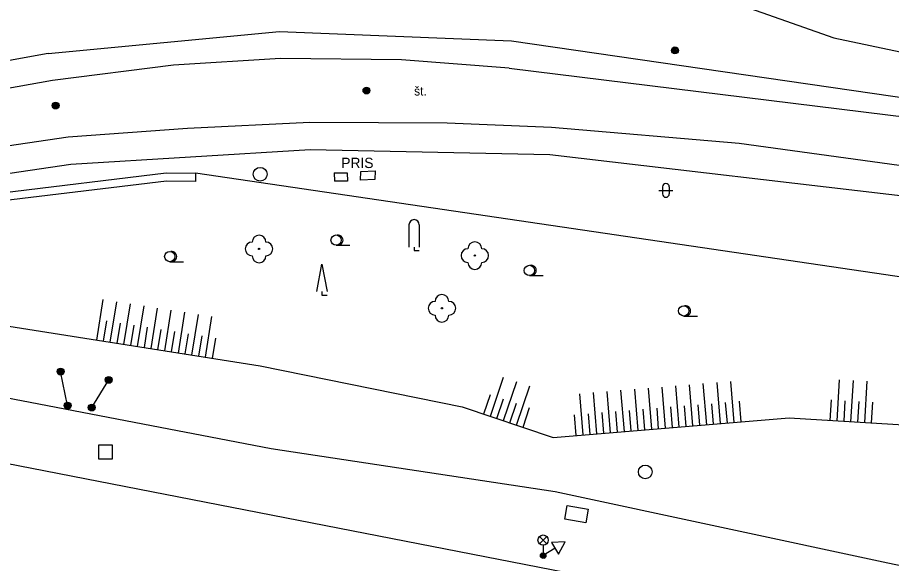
# Model space of a CAD drawing. Extents: x -599951 to -598963, y -1164095 to -1162939.
# Drawn here: x -599846.5 to -599783, y -1163048.3 to -1163008.7 of the extents above; entities that cross this region are included whole.
import ezdxf

# ---------------------------------------------------------------- set-up
doc = ezdxf.new("R2010")
doc.units = 0
for name, color, linetype in [('Level 10', 7, 'Continuous'), ('Level 11', 7, 'Continuous'), ('Level 13', 7, 'Continuous'), ('Level 14', 7, 'Continuous'), ('Level 15', 7, 'Continuous'), ('Level 22', 7, 'Continuous'), ('Level 24', 7, 'Continuous'), ('Level 25', 7, 'Continuous'), ('Level 26', 7, 'Continuous'), ('Level 27', 7, 'Continuous'), ('Level 33', 7, 'Continuous'), ('Level 34', 7, 'Continuous'), ('Level 36', 7, 'Continuous'), ('Level 40', 7, 'Continuous'), ('Level 41', 7, 'Continuous'), ('Level 7', 7, 'Continuous')]:
    doc.layers.add(name, color=color, linetype=linetype)

msp = doc.modelspace()

# ---------------------------------------------------------------- linework, layer by layer
at = {"layer": 'Level 10'}
msp.add_lwpolyline([(-599860, -1163038.58), (-599806.72, -1163048.96)], dxfattribs=at)
at = {"layer": 'Level 11'}
for points in [[(-599844.28, -1163011.27), (-599827.48, -1163009.67)], [(-599827.48, -1163009.67), (-599810.62, -1163010.35)], [(-599810.62, -1163010.35), (-599779.77, -1163014.83)], [(-599844.28, -1163011.27), (-599863.42, -1163014.74)], [(-599842.62, -1163019.32), (-599825.24, -1163018.26)], [(-599825.24, -1163018.26), (-599807.84, -1163018.62)], [(-599807.84, -1163018.62), (-599780.96, -1163021.77)], [(-599852.17, -1163020.73), (-599842.62, -1163019.32)], [(-599842.86, -1163036.86), (-599843.37, -1163034.39)], [(-599783.29, -1163048.32), (-599807.46, -1163043.13), (-599828.09, -1163040.01), (-599852.4, -1163035.32)], [(-599841.11, -1163037), (-599839.88, -1163034.99)], [(-599806.58, -1163044.13), (-599805.07, -1163044.39), (-599805.24, -1163045.38), (-599806.75, -1163045.12), (-599806.58, -1163044.13)], [(-599752.45, -1163054.58), (-599771.39, -1163050.77), (-599783.29, -1163048.32)]]:
    msp.add_lwpolyline(points, dxfattribs=at)
at = {"layer": 'Level 13'}
for points in [[(-599827.41, -1163011.65), (-599835.18, -1163012.12)], [(-599818.61, -1163011.73), (-599827.41, -1163011.65)], [(-599810.8, -1163012.34), (-599818.61, -1163011.73)], [(-599835.18, -1163012.12), (-599843.96, -1163013.24)], [(-599810.8, -1163012.34), (-599779.96, -1163016.14)], [(-599843.96, -1163013.24), (-599853.58, -1163014.95)], [(-599834.15, -1163016.7), (-599825.28, -1163016.27)], [(-599825.28, -1163016.27), (-599815.29, -1163016.32)], [(-599815.29, -1163016.32), (-599807.72, -1163016.62)], [(-599842.82, -1163017.33), (-599834.15, -1163016.7)], [(-599807.72, -1163016.62), (-599794.09, -1163017.79)], [(-599852.52, -1163018.77), (-599842.82, -1163017.33)], [(-599794.09, -1163017.79), (-599780.54, -1163019.65)]]:
    msp.add_lwpolyline(points, dxfattribs=at)
at = {"layer": 'Level 14'}
for points in [[(-599808.34, -1163001.79), (-599796.36, -1163006.89), (-599787.21, -1163010.15), (-599762.56, -1163015.35), (-599750.18, -1163017.87)], [(-599768.65, -1163029.54), (-599833.57, -1163019.98)], [(-599850.84, -1163030.51), (-599828.89, -1163033.97), (-599814.2, -1163036.96), (-599807.6, -1163039.17), (-599790.47, -1163037.76), (-599781.75, -1163038.28), (-599775.55, -1163038.66), (-599752.45, -1163054.58)]]:
    msp.add_lwpolyline(points, dxfattribs=at)
at = {"layer": 'Level 15'}
for points in [[(-599840.74, -1163032.1), (-599840.28, -1163029.15)], [(-599839.76, -1163032.26), (-599839.29, -1163029.31)], [(-599838.77, -1163032.41), (-599838.3, -1163029.46)], [(-599837.78, -1163032.57), (-599837.31, -1163029.62)], [(-599836.79, -1163032.72), (-599836.33, -1163029.77)], [(-599835.81, -1163032.88), (-599835.34, -1163029.92)], [(-599834.82, -1163033.04), (-599834.35, -1163030.08)], [(-599833.83, -1163033.19), (-599833.36, -1163030.23)], [(-599840.25, -1163032.18), (-599840.02, -1163030.7)], [(-599839.26, -1163032.34), (-599839.03, -1163030.86)], [(-599838.27, -1163032.49), (-599838.04, -1163031.01)], [(-599832.84, -1163033.35), (-599832.38, -1163030.39)], [(-599837.29, -1163032.65), (-599837.05, -1163031.17)], [(-599836.3, -1163032.8), (-599836.07, -1163031.32)], [(-599835.31, -1163032.96), (-599835.08, -1163031.48)], [(-599834.32, -1163033.11), (-599834.09, -1163031.64)], [(-599833.34, -1163033.27), (-599833.1, -1163031.79)], [(-599832.35, -1163033.43), (-599832.11, -1163031.95)], [(-599812.16, -1163037.63), (-599811.2, -1163034.79)], [(-599811.21, -1163037.95), (-599810.25, -1163035.11)], [(-599810.26, -1163038.27), (-599809.3, -1163035.43)], [(-599798.44, -1163038.42), (-599798.69, -1163035.43)], [(-599797.45, -1163038.33), (-599797.69, -1163035.34)], [(-599796.45, -1163038.25), (-599796.7, -1163035.26)], [(-599795.45, -1163038.17), (-599795.7, -1163035.18)], [(-599794.46, -1163038.09), (-599794.7, -1163035.1)], [(-599786.98, -1163037.97), (-599786.8, -1163034.99)], [(-599785.98, -1163038.03), (-599785.8, -1163035.04)], [(-599784.98, -1163038.09), (-599784.8, -1163035.09)], [(-599812.63, -1163037.47), (-599812.15, -1163036.05)], [(-599805.42, -1163038.99), (-599805.67, -1163036)], [(-599804.42, -1163038.91), (-599804.67, -1163035.92)], [(-599803.43, -1163038.83), (-599803.67, -1163035.84)], [(-599802.43, -1163038.74), (-599802.68, -1163035.75)], [(-599801.43, -1163038.66), (-599801.68, -1163035.67)], [(-599800.44, -1163038.58), (-599800.68, -1163035.59)], [(-599799.44, -1163038.5), (-599799.69, -1163035.51)], [(-599811.69, -1163037.79), (-599811.2, -1163036.37)], [(-599810.74, -1163038.11), (-599810.26, -1163036.69)], [(-599795.95, -1163038.21), (-599796.07, -1163036.72)], [(-599794.95, -1163038.13), (-599795.08, -1163036.63)], [(-599793.96, -1163038.05), (-599794.08, -1163036.55)], [(-599787.48, -1163037.94), (-599787.39, -1163036.45)], [(-599786.48, -1163038), (-599786.39, -1163036.51)], [(-599785.48, -1163038.06), (-599785.39, -1163036.56)], [(-599784.48, -1163038.12), (-599784.39, -1163036.62)], [(-599809.79, -1163038.43), (-599809.31, -1163037.01)], [(-599802.93, -1163038.78), (-599803.05, -1163037.29)], [(-599801.93, -1163038.7), (-599802.05, -1163037.21)], [(-599800.94, -1163038.62), (-599801.06, -1163037.13)], [(-599799.94, -1163038.54), (-599800.06, -1163037.04)], [(-599798.94, -1163038.46), (-599799.06, -1163036.96)], [(-599797.94, -1163038.38), (-599798.07, -1163036.88)], [(-599796.95, -1163038.29), (-599797.07, -1163036.8)], [(-599805.92, -1163039.03), (-599806.04, -1163037.54)], [(-599804.92, -1163038.95), (-599805.04, -1163037.45)], [(-599803.92, -1163038.87), (-599804.05, -1163037.37)]]:
    msp.add_lwpolyline(points, dxfattribs=at)
at = {"layer": 'Level 22'}
for centre in [(-599828.96, -1163025.48), (-599813.29, -1163025.96), (-599815.68, -1163029.79)]:
    msp.add_circle(centre, 0.05, dxfattribs=at)
for centre, start, end in [((-599828.96, -1163024.98), 0, 180), ((-599829.46, -1163025.48), 90, 270), ((-599828.46, -1163025.48), 270, 90), ((-599813.29, -1163025.46), 0, 180), ((-599813.79, -1163025.96), 90, 270), ((-599812.79, -1163025.96), 270, 90), ((-599828.96, -1163025.98), 180, 0), ((-599813.29, -1163026.46), 180, 0), ((-599815.68, -1163029.29), 0, 180), ((-599816.18, -1163029.79), 90, 270), ((-599815.18, -1163029.79), 270, 90), ((-599815.68, -1163030.29), 180, 0)]:
    msp.add_arc(centre, 0.5, start, end, dxfattribs=at)
at = {"layer": 'Level 24'}
for points in [[(-599823.51, -1163019.96), (-599822.55, -1163019.96), (-599822.53, -1163020.55), (-599823.49, -1163020.55)], [(-599823.51, -1163019.96), (-599823.49, -1163020.55)], [(-599821.58, -1163019.85), (-599820.53, -1163019.81), (-599820.54, -1163020.44), (-599821.59, -1163020.48), (-599821.58, -1163019.85)]]:
    msp.add_lwpolyline(points, dxfattribs=at)
at = {"layer": 'Level 25'}
for centre, radius in [((-599798.76, -1163011.05), 0.25), ((-599798.76, -1163011.05), 0.2), ((-599798.76, -1163011.05), 0.15), ((-599798.76, -1163011.05), 0.1), ((-599798.76, -1163011.05), 0.05), ((-599821.16, -1163013.97), 0.25), ((-599821.16, -1163013.97), 0.2), ((-599821.16, -1163013.97), 0.15), ((-599821.16, -1163013.97), 0.1), ((-599821.16, -1163013.97), 0.05), ((-599843.73, -1163015.06), 0.25), ((-599843.73, -1163015.06), 0.2), ((-599843.73, -1163015.06), 0.15), ((-599843.73, -1163015.06), 0.1), ((-599843.73, -1163015.06), 0.05), ((-599843.37, -1163034.39), 0.25), ((-599843.37, -1163034.39), 0.2), ((-599843.37, -1163034.39), 0.15), ((-599843.37, -1163034.39), 0.1), ((-599843.37, -1163034.39), 0.05), ((-599839.88, -1163034.99), 0.25), ((-599839.88, -1163034.99), 0.2), ((-599839.88, -1163034.99), 0.15), ((-599839.88, -1163034.99), 0.1), ((-599839.88, -1163034.99), 0.05), ((-599842.86, -1163036.86), 0.25), ((-599842.86, -1163036.86), 0.2), ((-599842.86, -1163036.86), 0.15), ((-599842.86, -1163036.86), 0.1), ((-599842.86, -1163036.86), 0.05), ((-599841.11, -1163037), 0.25), ((-599841.11, -1163037), 0.2), ((-599841.11, -1163037), 0.15), ((-599841.11, -1163037), 0.1), ((-599841.11, -1163037), 0.05)]:
    msp.add_circle(centre, radius, dxfattribs=at)
at = {"layer": 'Level 26'}
msp.add_lwpolyline([(-599840.61, -1163040.74), (-599839.61, -1163040.74), (-599839.61, -1163039.74), (-599840.61, -1163039.74)], close=True, dxfattribs=at)
at = {"layer": 'Level 27'}
for centre in [(-599828.88, -1163020.05), (-599800.91, -1163041.68)]:
    msp.add_circle(centre, 0.5, dxfattribs=at)
at = {"layer": 'Level 33'}
for p, q in [((-599808.595, -1163046.9), (-599808.065, -1163046.37)), ((-599808.595, -1163046.37), (-599808.065, -1163046.9)), ((-599808.33, -1163047.01), (-599808.33, -1163047.76))]:
    msp.add_line(p, q, dxfattribs=at)
for centre, radius in [((-599808.33, -1163046.635), 0.375), ((-599808.33, -1163047.76), 0.2), ((-599808.33, -1163047.76), 0.145), ((-599808.33, -1163047.76), 0.0876)]:
    msp.add_circle(centre, radius, dxfattribs=at)
at = {"layer": 'Level 34'}
for p, q in [((-599807.466, -1163047.221), (-599808.33, -1163047.76)), ((-599808.462, -1163047.548), (-599808.198, -1163047.972))]:
    msp.add_line(p, q, dxfattribs=at)
msp.add_lwpolyline([(-599807.731, -1163046.797), (-599807.202, -1163047.645), (-599806.732, -1163046.762)], close=True, dxfattribs=at)
at = {"layer": 'Level 36'}
for p, q in [((-599799.916, -1163021.226), (-599798.916, -1163021.226)), ((-599799.666, -1163020.976), (-599799.666, -1163021.476)), ((-599799.166, -1163020.976), (-599799.166, -1163021.476)), ((-599818.075, -1163023.725), (-599818.075, -1163025.35)), ((-599817.325, -1163023.725), (-599817.325, -1163025.35)), ((-599823.36, -1163025.215), (-599822.36, -1163025.215)), ((-599835.44, -1163026.405), (-599834.44, -1163026.405)), ((-599809.33, -1163027.415), (-599808.33, -1163027.415)), ((-599798.12, -1163030.355), (-599797.12, -1163030.355))]:
    msp.add_line(p, q, dxfattribs=at)
for points in [[(-599817.7, -1163025.35), (-599817.7, -1163025.6), (-599817.325, -1163025.6)], [(-599824.775, -1163028.58), (-599824.4, -1163026.58), (-599824.025, -1163028.58)], [(-599824.4, -1163028.58), (-599824.4, -1163028.83), (-599824.025, -1163028.83)]]:
    msp.add_lwpolyline(points, dxfattribs=at)
for centre in [(-599823.36, -1163024.84), (-599835.44, -1163026.03), (-599809.33, -1163027.04), (-599798.12, -1163029.98)]:
    msp.add_circle(centre, 0.375, dxfattribs=at)
for centre, radius, start, end in [((-599799.416, -1163020.976), 0.25, 0, 180), ((-599799.416, -1163021.476), 0.25, 180, 0), ((-599817.7, -1163023.725), 0.375, 0, 180), ((-599823.235, -1163024.84), 0.375, 260.40593, 99.59407), ((-599835.315, -1163026.03), 0.375, 260.40593, 99.59407), ((-599809.205, -1163027.04), 0.375, 260.40593, 99.59407), ((-599797.995, -1163029.98), 0.375, 260.40593, 99.59407)]:
    msp.add_arc(centre, radius, start, end, dxfattribs=at)
at = {"layer": 'Level 7'}
for points in [[(-599861.31, -1163023.81), (-599847.64, -1163021.4), (-599835.7, -1163019.95), (-599833.57, -1163019.98)], [(-599833.57, -1163019.98), (-599833.58, -1163020.58), (-599835.67, -1163020.55), (-599847.55, -1163021.99), (-599861.17, -1163024.39)]]:
    msp.add_lwpolyline(points, dxfattribs=at)

# ---------------------------------------------------------------- texts
at = {"layer": 'Level 40'}
msp.add_text('št.', height=0.65, dxfattribs=at).set_placement((-599817.7, -1163014.33))
at = {"layer": 'Level 41'}
msp.add_text('PRIS', height=0.75, dxfattribs=at).set_placement((-599822.99, -1163019.6))

doc.saveas('drawing.dxf')
